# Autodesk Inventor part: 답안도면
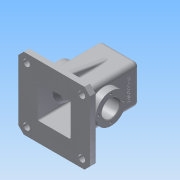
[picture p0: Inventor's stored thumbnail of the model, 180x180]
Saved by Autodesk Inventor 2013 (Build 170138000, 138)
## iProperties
Created: 2016-02
Part Number: 답안도면
Material: 알루미늄 6061
Document SubType Name: Modeling
Designer: Administrator
Density: 2.71 g/cm^3
Mass: 932.551 g
Surface Area: 1044.04 cm^2
Volume: 344.115 cm^3
Author: Administrator
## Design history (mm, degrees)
sketch "스케치1"
  geometry: L1 (35, 0)-(-35, 0); L2 (-35, 0)-(-35, 120); L3 (-35, 120)-(35, 120); L4 (35, 120)-(35, 0); 2 further points
  constraints: 8 end point, 2 coincident, 2 parallel, 1 horizontal, 1 midpoint, 1 perpendicular
  dimensions: "d0" = 70 distance of L2.end L3.end; "d3" = 120 distance of L3.end L1.start
extrude "돌출1" new body sketch "스케치1" stored distance "d4" = 70; taper "d5" = 0 deg
sketch "스케치2"
  geometry: L1 (-30, 30)-(100, 30); L2 (100, 30)-(100, -100); L3 (100, -100)-(-30, -100); L4 (-30, -100)-(-30, 30); 3 further points
  constraints: 8 end point, 2 midpoint, 2 parallel, 1 horizontal, 1 horizontal alignment, 1 perpendicular, 1 vertical alignment
  dimensions: "d6" = 130 distance of L1.end L2.end; "d8" = 130 distance of L1.start L1.end
extrude "돌출2" join sketch "스케치2" distance "d9" = 10; taper "d10" = 0 deg
node "작업 평면1"
sketch "스케치3"
  geometry: L1 (-30, -120)-(100, -120) reference; C1 r 27.5 at (35, -65); 2 further points
  constraints: 1 centre point, 1 midpoint, 1 vertical alignment
  dimensions: "d12" = 55 diameter of C1; "d14" = 55 distance from line of L1 C1.centre
extrude "돌출3" join sketch "스케치3" distance "d15" = 96; taper "d16" = 0 deg
hole "구멍1" diameter "d19" = 32; stored, may be unused: countersink angle "d23" = 90 deg, drill point angle "d25" = 0 deg; dims "d17" = 10, "d18" = 10, "d20" = 6, "d21" = 4, "d22" = 2, "d24" = 8
sketch "스케치4"
  geometry: L1 (-35, 10)-(-35, 120) reference; L2 (-35, 120)-(35, 120) reference; L3 (35, 120)-(35, 10) reference; L4 (30, 0)-(30, 115); L5 (30, 115)-(-30, 115); L6 (-30, 115)-(-30, 0); L7 (65, 0)-(-65, 0) reference; L8 (-30, 0)-(30, 0); 1 further point
  constraints: 8 end point, 2 point on line, 1 collinear
  dimensions: "d26" = 5 distance between parallel lines of L5 L2; "d27" = 5 distance between parallel lines of L4 L3; "d28" = 5 distance between parallel lines of L1 L6
extrude "돌출4" cut sketch "스케치4" stored distance "d29" = 60; taper "d30" = 0 deg
sketch "스케치5"
  geometry: L1 (-30, 0)-(-30, 115) reference; L2 (30, 115)-(30, 0) reference; L3 (48, 71)-(30, 71) reference; L4 (48, 39)-(30, 39) reference; L5 (-30, 71)-(-48, 71) reference; L6 (-30, 39)-(-48, 39) reference; L7 (-30, 82.5)-(-23, 75.5); L8 (-23, 75.5)-(-23, 71); L9 (-23, 71)-(-30, 71); L10 (-68.044, 55)-(90.6, 55); L11 (30, 82.5)-(23, 75.5); L12 (23, 75.5)-(23, 71); L13 (23, 71)-(30, 71); L14 (30, 0)-(-30, 0) reference; L15 (30, 71)-(30, 82.5); L16 (-30, 71)-(-30, 82.5); 1 further point
  constraints: 18 end point, 4 parallel, 2 perpendicular, 2 point on line, 1 collinear, 1 horizontal
  dimensions: "d31" = 55 distance between parallel lines of L14 L10; "d32" = 135 deg angle of L7 L1; "d33" = 135 deg angle of L11 L2 (derived); "d34" = 7 distance between parallel lines of L1 L8; "d35" = 7 distance between parallel lines of L12 L2; "d36" = 55 diameter of L7.start L10; "d37" = 55 diameter of L11.start L10
revolve "회전1" sketch "스케치5" stored, may be unused: angle "d38" = 90 deg
fillet "모깎기1" dims "d39" = 3
fillet "모깎기2" dims "d40" = 3
fillet "모깎기3" dims "d41" = 8
fillet "모깎기4" dims "d42" = 8
sketch "스케치7"
  geometry: L1 (-27, 120)-(27, 120) reference; L2 (0, 120)-(0, 138.989); L3 (-20, 120)-(-18.237, 130); L4 (-18.237, 130)-(0, 130); L5 (-30, 112)-(-30, 60.22) reference; L6 (-20, 120)-(0, 120); 1 further point
  constraints: 8 end point, 2 perpendicular, 2 point on line, 1 collinear, 1 midpoint, 1 vertical alignment
  dimensions: "d44" = 40 diameter of L3.start L2; "d46" = 10 distance between parallel lines of L1 L4; "d47" = 10 deg angle of L5 L3
revolve "회전2" sketch "스케치7" stored, may be unused: angle "d48" = 90 deg
hole "구멍2" diameter "d51" = 28; stored, may be unused: countersink angle "d55" = 90 deg, drill point angle "d57" = 0 deg; dims "d49" = 10, "d50" = 10, "d52" = 6, "d53" = 4, "d54" = 2, "d56" = 4
hole "구멍3" diameter "d60" = 21; stored, may be unused: countersink angle "d64" = 90 deg, drill point angle "d66" = 0 deg; dims "d58" = 10, "d59" = 10, "d61" = 6, "d62" = 4, "d63" = 2, "d65" = 4
sketch "스케치8" dims "d67" = 45
  geometry: C1 r 27.5 at (0, 0) reference; 3 further points
  constraints: 2 vertical alignment, 1 coincident, 2 other
hole "구멍4" sketch "스케치8" at (0, 22.5) diameter "d69" = 3.459; stored, may be unused: countersink angle "d73" = 90 deg, drill point angle "d75" = 118 deg; dims "d70" = 8, "d71" = 4, "d72" = 2, "d74" = 10
sketch "스케치10" dims "d79" = 45
  geometry: C1 r 27.5 at (0, 0) reference; 3 further points
  constraints: 2 vertical alignment, 1 coincident, 2 other
hole "구멍5" sketch "스케치10" at (0, 22.5) diameter "d81" = 3.459; stored, may be unused: countersink angle "d85" = 90 deg, drill point angle "d87" = 118 deg; dims "d82" = 8, "d83" = 4, "d84" = 2, "d86" = 10
fillet "모깎기5" dims "d91" = 3
chamfer "모따기1" distance "d92" = 10; stored, may be unused: second distance "d93" = 2, angle "d94" = 45 deg
sketch "스케치11"
  geometry: L1 (-15, 85)-(85, 85); L2 (85, 85)-(85, -15); L3 (85, -15)-(-15, -15); L4 (-15, -15)-(-15, 85); C1 r 6 at (-15, 85); C2 r 6 at (85, 85); C3 r 6 at (-15, -15); C4 r 6 at (85, -15); 3 further points
  constraints: 8 end point, 4 centre point, 4 coincident, 2 midpoint, 2 parallel, 1 horizontal, 1 horizontal alignment, 1 perpendicular, 1 vertical alignment
  dimensions: "d95" = 100 distance of L1.end L2.end; "d97" = 100 distance of L1.start L1.end; "d98" = 12 diameter of C1; "d99" = 12 diameter of C2; "d100" = 12 diameter of C4; "d101" = 12 diameter of C3
extrude "돌출5" cut sketch "스케치11" stored distance "d102" = 60; taper "d103" = 0 deg
sketch "스케치12"
  geometry: L1 (10, 35)-(112, 35) reference; L2 (10, -55)-(10, 55) reference; L3 (112, -35)-(10, -35) reference; L4 (95.069, 35)-(10, 50); L5 (95.069, -35)-(10, -50); L6 (0, 65)-(10, 65) reference; L7 (10, 65)-(10, 55) reference; L8 (10, 56)-(10, 44) reference; L9 (10, -65)-(0, -65) reference; 1 further point
  constraints: 4 end point, 3 point on line, 1 midpoint
  dimensions: "d104" = 15 distance from line of L4.end L6; "d105" = 15 distance from line of L9 L5.end; "d106" = 10 deg angle of L4 L6; "d107" = 10 deg angle of L5 L9
extrude "돌출6" join sketch "스케치12" stored distance "d108" = 10; taper "d109" = 0 deg
fillet "모깎기8" dims "d112" = 3
fillet "모깎기9" dims "d113" = 3
fillet "모깎기10" dims "d114" = 3
fillet "모깎기11" dims "d115" = 3
fillet "모깎기12" dims "d116" = 3
chamfer "모따기2" distance "d117" = 1; stored, may be unused: second distance "d118" = 2, angle "d119" = 45 deg
chamfer "모따기3" distance "d120" = 1; stored, may be unused: second distance "d121" = 2, angle "d122" = 45 deg
sketch "스케치14"
  geometry: L1 (18.237, 75)-(-18.237, 75) reference; 3 further points
  constraints: 1 midpoint, 1 vertical alignment, 1 other
  dimensions: "d123" = 30 distance from line of point (0, 45) L1
feature "엠보싱1" sketch "스케치14" dims "d124" = 0.5, "d125" = 0
fillet "모깎기13" dims "d126" = 0.5
fillet "모깎기16" dims "d129" = 0.5
fillet "모깎기17" dims "d130" = 0.5
node "솔리드1"
pattern_circular "원형 패턴1" dims angle "d77" = 360 deg
pattern_circular "원형 패턴2" dims angle "d89" = 360 deg
other parameters: "d11" = 13
